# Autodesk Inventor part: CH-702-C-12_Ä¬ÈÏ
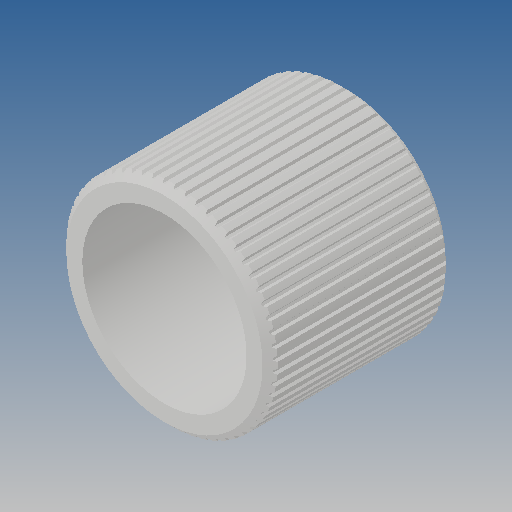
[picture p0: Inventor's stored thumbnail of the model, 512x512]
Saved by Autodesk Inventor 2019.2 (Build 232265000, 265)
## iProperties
Created: 2010-06
Part Number: CH-702-C-12_Ä¬ÈÏ
Material: Ogólny
Document SubType Name: Modeling
Designer: CADENGINEERING4
Density: 1 g/cm^3
Appearance: Domyślna
Author: CADENGINEERING4
Revision Number: ÈÎºÎ
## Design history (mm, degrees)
feature "NONE"
node "Bryła1"
